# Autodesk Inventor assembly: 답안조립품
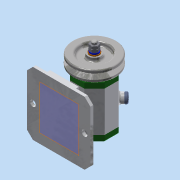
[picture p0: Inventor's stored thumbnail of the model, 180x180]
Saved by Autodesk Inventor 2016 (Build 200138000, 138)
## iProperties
Created: 2018-06
Part Number: 답안조립품
Material: 일반
Document SubType Name: Assembly
Designer: 605-11
Author: 605-11
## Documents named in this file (16)
- C:\Users\605-11\Desktop\480607V1003\답안조립품.iam
- C:\Users\605-11\Desktop\480607V1003\V벨트풀리.ipt
- C:\Users\605-11\Desktop\480607V1003\고무캡.ipt
- C:\Users\605-11\Desktop\480607V1003\너트 M8.ipt
- 너트 M8.ipt
- C:\Users\605-11\Desktop\480607V1003\뒤커버.ipt
- C:\Users\605-11\Desktop\480607V1003\베어링 15x32x9.ipt
- C:\Users\605-11\Desktop\480607V1003\볼트 M4x12.ipt
- C:\Users\605-11\Desktop\480607V1003\스프링와셔 8.ipt
- C:\Users\605-11\Desktop\480607V1003\앞커버.ipt
- C:\Users\605-11\Desktop\480607V1003\오일 실 15 25 7.ipt
- C:\Users\605-11\Desktop\480607V1003\와셔 8x17.ipt
- C:\Users\605-11\Desktop\480607V1003\축.ipt
- C:\Users\605-11\Desktop\480607V1003\키 3x3x12.ipt
- 키 3x3x12.ipt
- C:\Users\605-11\Desktop\480607V1003\본체.ipt
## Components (2 placed, 2 different names)
1. V벨트풀리:1
2. 고무캡:1
